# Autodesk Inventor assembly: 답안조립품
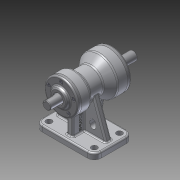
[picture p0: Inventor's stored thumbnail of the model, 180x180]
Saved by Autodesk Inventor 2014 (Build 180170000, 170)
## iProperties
Created: 2015-08
Part Number: 답안조립품
Document SubType Name: Assembly
Designer: USER
Author: USER
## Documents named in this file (10)
- C:\Users\USER\Desktop\450805V1012\답안조립품.iam
- C:\Users\USER\Desktop\450805V1012\M4x0.5.ipt
- C:\Users\USER\Desktop\450805V1012\뒤커버.ipt
- C:\Users\USER\Desktop\450805V1012\베어링 6203.ipt
- C:\Users\USER\Desktop\450805V1012\베어링 6205.ipt
- C:\Users\USER\Desktop\450805V1012\본체.ipt
- C:\Users\USER\Desktop\450805V1012\앞커버.ipt
- C:\Users\USER\Desktop\450805V1012\오일실 .ipt
- 오일실 .ipt
- C:\Users\USER\Desktop\450805V1012\축.ipt
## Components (10 placed, 1 different names)
1. M4x0.5:1
2. M4x0.5:3
3. M4x0.5:4
4. M4x0.5:5
5. M4x0.5:6
6. M4x0.5:2
7. M4x0.5:7
8. M4x0.5:8
9. M4x0.5:9
10. M4x0.5:10
